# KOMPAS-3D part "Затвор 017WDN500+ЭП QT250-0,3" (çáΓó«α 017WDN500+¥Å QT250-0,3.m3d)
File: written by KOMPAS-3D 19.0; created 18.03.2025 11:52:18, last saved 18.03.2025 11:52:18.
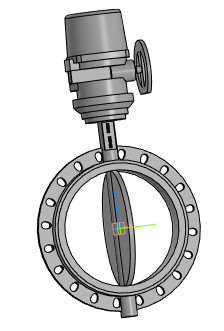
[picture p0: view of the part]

Document properties: Полное имя файла: Затвор 017WDN500+ЭП QT250-0,3.a3d

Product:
- Part/product: Затвор 017WDN500+ЭП QT250-0,3
    Масса: 301.439

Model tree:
1. Операция без истории:1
